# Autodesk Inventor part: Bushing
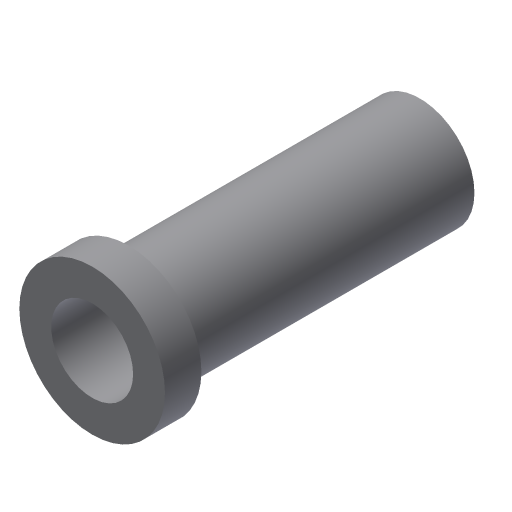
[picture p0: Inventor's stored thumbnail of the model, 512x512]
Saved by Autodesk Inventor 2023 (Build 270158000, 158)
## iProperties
Shininess: 77.0
Length Units: 11269
Angle Units: 11279
Time Units: 11290
Mass Units: 11283
Length Display Precision: 3
Angle Display Precision: 2
Created: 2002-02
Part Number: Bushing
Document SubType Name: Modeling
Designer: ***
Density: 1 g/cm^3
Material: Generic
Appearance: Default
Density: 0.0
Volumn: 0.0
Area: 0.0
PropertySet Name: Model Information
Control State: 0
Master: False
Checked Out: False
Author: ***
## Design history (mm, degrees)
sketch "Sketch1"
  geometry: L1 (6.25, 50.44)-(6.25, 5.44); L2 (6.25, 5.44)-(10.625, 5.44); L3 (10.625, 5.44)-(10.625, 10.44); L4 (10.625, 10.44)-(8.125, 10.44); L5 (8.125, 10.44)-(8.125, 50.44); L6 (8.125, 50.44)-(6.25, 50.44); L7 (0.625, 34.884)-(0.625, 0)
  constraints: 14 end point, 4 parallel, 2 perpendicular, 1 vertical
  dimensions: "d0" = 20 diameter of L3 L7; "d1" = 11.25 diameter of L1 L7; "d2" = 15 diameter of L5 L7; "d4" = 5 distance of L2.end L3.end; "d5" = 45 distance of L1.start L1.end
revolve "Revolution1" sketch "Sketch1" stored, may be unused: angle "d3" = 90 deg
body "Solid1"
